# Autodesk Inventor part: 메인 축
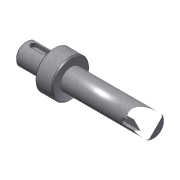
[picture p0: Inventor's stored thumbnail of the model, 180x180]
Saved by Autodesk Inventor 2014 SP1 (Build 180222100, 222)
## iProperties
Created: 2012-07
Part Number: 메인 축
Document SubType Name: Modeling
Designer: SeoGD™ [www.esajin.kr]
Density: 1 g/cm^3
Material: 일반
Appearance: 금속-강(스테인리스, 브러시됨)
Author: SeoGD™ [www.esajin.kr]
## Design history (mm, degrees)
sketch "스케치1"
  geometry: L1 (0, 0)-(102, 0); L2 (0, -8.5)-(22, -8.5); L3 (22, -15)-(36.003, -15); L4 (36.003, -8.5)-(102, -8.5); L5 (102, -8.5)-(102, 0); L6 (0, -8.5)-(0, 0); L7 (36.003, -15)-(36.003, -8.5); L8 (22, -15)-(22, -8.5); L9 (36.003, -26)-(36.003, 26) reference; 1 further point
  constraints: 16 end point, 2 parallel, 2 perpendicular, 1 coincident, 1 collinear, 1 horizontal
  dimensions: "d0" = 17 diameter of L4 L1; "d1" = 30 diameter of L3 L1; "d2" = 22 distance of L2.start L2.end; "d3" = 65.99692 distance of L4.start L4.end (derived); "d5" = 17 diameter of L2 L1; "d19" = 80 distance between parallel lines of L8 L5
revolve "회전1" sketch "스케치1" stored, may be unused: angle "d4" = 90 deg
chamfer "모따기1" distance "d6" = 1; stored, may be unused: second distance "d7" = 2, angle "d8" = 45 deg
node "작업 평면1"
sketch "스케치2"
  geometry: L1 (-11, -7.5)-(-11, 7.5) reference; L2 (-4.5, 2.5)-(4.5, 2.5); L3 (4.5, -2.5)-(-4.5, -2.5); A1 r 2.5 centre (4.5, 0) between (4.5, -2.5) and (4.5, 2.5); A2 r 2.5 centre (-4.5, 0) between (-4.5, 2.5) and (-4.5, -2.5); 2 further points
  constraints: 4 end point, 4 point on circle, 4 tangent, 2 centre point, 1 horizontal alignment, 1 midpoint, 1 parallel, 1 perpendicular
  dimensions: "d9" = 5 distance between parallel lines of L3 L2; "d10" = 14 dimension on A1 A2; "d11" = 4 distance edge to line of A2 L1
extrude "돌출1" cut sketch "스케치2" distance "d12" = 3; taper "d13" = 0 deg
node "작업 평면2"
sketch "스케치3"
  geometry: L1 (32.998, 7.5)-(32.998, -7.5) reference; L2 (32.998, 2.5)-(17.498, 2.5); L3 (17.498, -2.5)-(32.998, -2.5); A1 r 2.5 centre (17.498, 0) between (17.498, 2.5) and (17.498, -2.5); 2 further points
  constraints: 4 end point, 2 perpendicular, 2 point on circle, 2 point on line, 2 tangent, 1 centre point, 1 horizontal alignment, 1 midpoint
  dimensions: "d14" = 5 distance between parallel lines of L3 L2; "d15" = 18 dimension on A1 L1
extrude "돌출2" cut sketch "스케치3" distance "d16" = 3; taper "d17" = 0 deg
node "솔리드1"
node "참조7"
